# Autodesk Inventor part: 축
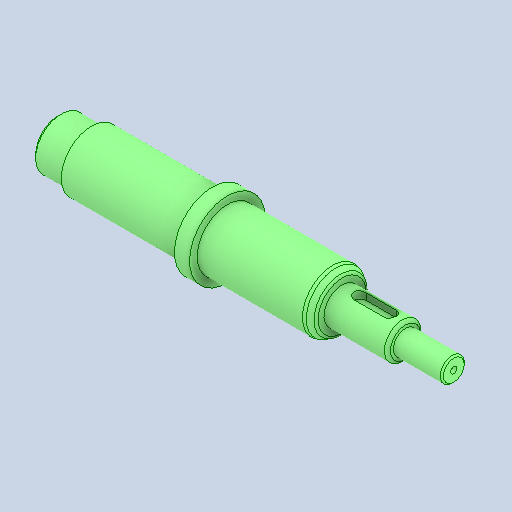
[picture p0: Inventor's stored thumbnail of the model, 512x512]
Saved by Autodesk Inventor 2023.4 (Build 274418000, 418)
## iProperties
Created: 2024-11
Part Number: 축
Material: 강철, 탄소
Document SubType Name: Modeling
Designer: EDU
Density: 7.85 g/cm^3
Appearance: 기본값
Author: jhkim
Sending System: Autodesk Inventor 2025
Preprocessor: ST-DEVELOPER v20
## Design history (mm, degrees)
feature "솔리드1"
node "솔리드2"
